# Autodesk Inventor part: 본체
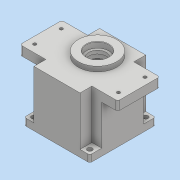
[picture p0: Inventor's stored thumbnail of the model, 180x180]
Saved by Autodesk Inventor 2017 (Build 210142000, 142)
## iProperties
Part Number: 본체
Material: 일반
Document SubType Name: Modeling
Designer: user
Density: 1 g/cm^3
Appearance: 기본값
Author: user
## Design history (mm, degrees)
sketch "스케치3"
  geometry: L1 (33, 47)-(-33, 47); L2 (-33, 47)-(-33, -47); L3 (-33, -47)-(33, -47); L4 (33, -47)-(33, 47); L5 (33, 47)-(-33, -47); L6 (-33, 47)-(33, -47); L7 (70, 30)-(-70, 30); L8 (-70, 30)-(-70, -30); L9 (-70, -30)-(70, -30); L10 (70, -30)-(70, 30); L11 (70, 30)-(-70, -30); L12 (-70, 30)-(70, -30); 1 further point
  constraints: 24 end point, 4 midpoint, 4 parallel, 2 horizontal, 2 perpendicular
  dimensions: "d12" = 66 distance of L3.end L2.end; "d13" = 94 distance of L2.end L1.end; "d14" = 140 distance of L9.end L8.end; "d15" = 60 distance of L8.end L7.end
extrude "돌출2" new body sketch "스케치3" distance "d16" = 13; taper "d17" = 0 deg
node "작업 평면1"
sketch "스케치4"
  geometry: L1 (-47, 47)-(47, 47); L2 (47, 47)-(47, -47); L3 (47, -47)-(-47, -47); L4 (-47, -47)-(-47, 47); L5 (-47, 47)-(47, -47); L6 (47, 47)-(-47, -47); 1 further point
  constraints: 12 end point, 2 midpoint, 2 parallel, 1 horizontal, 1 perpendicular
  dimensions: "d19" = 94 distance of L2.end L3.end; "d20" = 94 distance of L1.end L2.end
extrude "돌출3" join sketch "스케치4" distance "d21" = 10; taper "d22" = 0 deg
sketch "스케치5"
  geometry: L1 (-33, -30)-(-33, -47) reference; L2 (33, 47)-(-33, 47); L3 (-33, 47)-(-33, -47); L4 (-33, -47)-(33, -47); L5 (33, -47)-(33, 47); L6 (33, 47)-(-33, -47); L7 (-33, 47)-(33, -47); L8 (-47, 47)-(-47, -47) reference; L9 (47, 30)-(-47, 30); L10 (-47, 30)-(-47, -30); L11 (-47, -30)-(47, -30); L12 (47, -30)-(47, 30); L13 (47, 30)-(-47, -30); L14 (-47, 30)-(47, -30); L15 (70, 30)-(33, 30) reference; 1 further point
  constraints: 24 end point, 4 midpoint, 4 parallel, 2 horizontal, 2 perpendicular, 2 point on line
extrude "돌출4" join sketch "스케치5" distance "d23" = 70; taper "d24" = 0 deg
sketch "스케치6"
  geometry: C1 r 27.5 at (0, 11); 1 further point
  constraints: 1 centre point, 1 vertical alignment
  dimensions: "d25" = 55 diameter of C1; "d26" = 11 distance of point (0, 0) C1.centre
extrude "돌출5" join sketch "스케치6" distance "d27" = 7; taper "d28" = 0 deg
hole "구멍1" diameter "d31" = 32; stored, may be unused: countersink angle "d35" = 90 deg, drill point angle "d37" = 0 deg; dims "d29" = 10, "d30" = 10, "d32" = 6, "d33" = 4, "d34" = 2, "d36" = 8.3
sketch "스케치7"
  geometry: C1 r 12.5 at (0, 0); C2 r 16 at (0, 0) reference; 1 further point
  constraints: 1 centre point, 1 concentric
  dimensions: "d38" = 25 diameter of C1
extrude "돌출6" cut sketch "스케치7" distance "d39" = 4.7; taper "d40" = 0 deg
sketch "스케치8"
  geometry: C1 r 17.5 at (0, 0); C2 r 16 at (0, 0) reference; 1 further point
  constraints: 1 centre point, 1 concentric
  dimensions: "d41" = 35 diameter of C1
extrude "돌출7" cut sketch "스케치8" distance "d42" = 10; taper "d43" = 0 deg
sketch "스케치9"
  geometry: C1 r 43 at (0, 0); 1 further point
  constraints: 2 coincident, 1 centre point
  dimensions: "d44" = 86 diameter of C1
extrude "돌출8" cut sketch "스케치9" distance "d45" = 9; taper "d46" = 0 deg
sketch "스케치10"
  geometry: C1 r 40 at (0, 0); C2 r 43 at (0, 0) reference; 1 further point
  constraints: 1 centre point, 1 concentric
  dimensions: "d47" = 80 diameter of C1
extrude "돌출9" cut sketch "스케치10" distance "d48" = 62; taper "d49" = 0 deg
sketch "스케치11"
  geometry: 2 further points
  dimensions: "d50" = 19 vertical distance of point (0, 0) point (-60, 19); "d51" = 60 horizontal distance of point (0, 0) point (-60, 19)
hole "구멍2" sketch "스케치11" at (-60, 19) diameter "d52" = 4.5; stored, may be unused: countersink angle "d56" = 90 deg, drill point angle "d58" = 0 deg; dims "d53" = 6, "d54" = 10, "d55" = 5, "d57" = 13
sketch "스케치12"
  geometry: 2 further points
  dimensions: "d65" = 40 horizontal distance of point (0, 0) point (40, 40); "d66" = 40 horizontal distance of point (0, 0) point (40, 40)
hole "구멍3" sketch "스케치12" at (40, 40) diameter "d67" = 7; stored, may be unused: countersink angle "d71" = 90 deg, drill point angle "d73" = 0 deg; dims "d68" = 6, "d69" = 10, "d70" = 5, "d72" = 30
sketch "스케치13"
  geometry: C1 r 21 at (0, 11); C2 r 15 at (0, -20); 1 further point
  constraints: 2 centre point, 2 vertical alignment
  dimensions: "d80" = 42 diameter of C1; "d81" = 30 diameter of C2; "d82" = 11 distance of point (0, 0) C1.centre; "d83" = 20 distance of C2.centre point (0, 0)
extrude "돌출10" join sketch "스케치13" distance "d84" = 7; taper "d85" = 0 deg
hole "구멍4" diameter "d88" = 35; stored, may be unused: countersink angle "d92" = 90 deg, drill point angle "d94" = 0 deg; dims "d86" = 10, "d87" = 10, "d89" = 6, "d90" = 10, "d91" = 5, "d93" = 10
sketch "스케치14"
  geometry: C1 r 11 at (0, -20); A1 r 15 centre (0, -20) between (-8.978, -7.984) and (8.978, -7.984) reference; 1 further point
  constraints: 1 centre point, 1 concentric
  dimensions: "d95" = 22 diameter of C1
extrude "돌출11" cut sketch "스케치14" distance "d96" = 7; taper "d97" = 0 deg
sketch "스케치15"
  geometry: C1 r 9.5 at (0, 0); C2 r 11 at (0, 0) reference; 1 further point
  constraints: 1 centre point, 1 concentric
  dimensions: "d98" = 19 diameter of C1
extrude "돌출12" cut sketch "스케치15" distance "d99" = 3; taper "d100" = 0 deg
fillet "모깎기1" dims "d101" = 3
fillet "모깎기2" dims "d102" = 3
fillet "모깎기3" dims "d103" = 3
sketch "스케치16"
  geometry: A1 r 4 centre (-36, 0) between (-36.19, -3.995) and (-36.19, 3.995); A2 r 40 centre (0, 0) between (-39.279, 7.559) and (-39.279, -7.559) reference; A3 r 3 centre (-36.333, 6.992) between (-39.279, 7.559) and (-36.19, 3.995); A4 r 3 centre (-36.333, -6.992) between (-36.19, -3.995) and (-39.279, -7.559); 1 further point
  constraints: 8 point on circle, 4 tangent, 3 centre point, 1 horizontal alignment
  dimensions: "d104" = 8 diameter of A1; "d105" = 36 distance of A1.centre point (0, 0); "d106" = 3 radius of A4; "d107" = 3 radius of A3
extrude "돌출13" join sketch "스케치16" stored distance "d108" = 3; taper "d109" = 0 deg
sketch "스케치17"
  geometry: A1 r 4 centre (-36, 0) between (-36.19, -3.995) and (-36.19, 3.995) reference; 2 further points
  constraints: 1 coincident
hole "구멍5" sketch "스케치17" at (-36, 0) diameter "d110" = 3.242; stored, may be unused: countersink angle "d114" = 90 deg, drill point angle "d116" = 118 deg; dims "d111" = 7, "d112" = 10, "d113" = 5, "d115" = 9
chamfer "모따기1" distance "d117" = 1; stored, may be unused: second distance "d118" = 2, angle "d119" = 45 deg
chamfer "모따기2" distance "d120" = 0.8; stored, may be unused: second distance "d121" = 2, angle "d122" = 45 deg
chamfer "모따기4" distance "d126" = 1; stored, may be unused: second distance "d127" = 2, angle "d128" = 30 deg
sketch "스케치18"
  geometry: L1 (-11, 80)-(77, 80) reference; L2 (5.5, -7)-(60.5, -7) reference; L3 (16.2, -7)-(49.8, -7) reference; 2 further points
  constraints: 1 vertical alignment, 1 other
  dimensions: "d129" = 40 distance from line of L1 point (33, 40)
feature "엠보싱1" sketch "스케치18" dims "d12" = 66, "d13" = 94, "d130" = 0.5, "d131" = 0
chamfer "모따기5" distance "d132" = 0.8; stored, may be unused: second distance "d133" = 2, angle "d134" = 30 deg
node "솔리드2"
pattern_linear "직사각형 패턴1" dims "d61" = 120, "d64" = 38
pattern_linear "직사각형 패턴2" dims "d76" = 80, "d79" = 80
mirror "미러1"
other parameters: "d18" = -67
